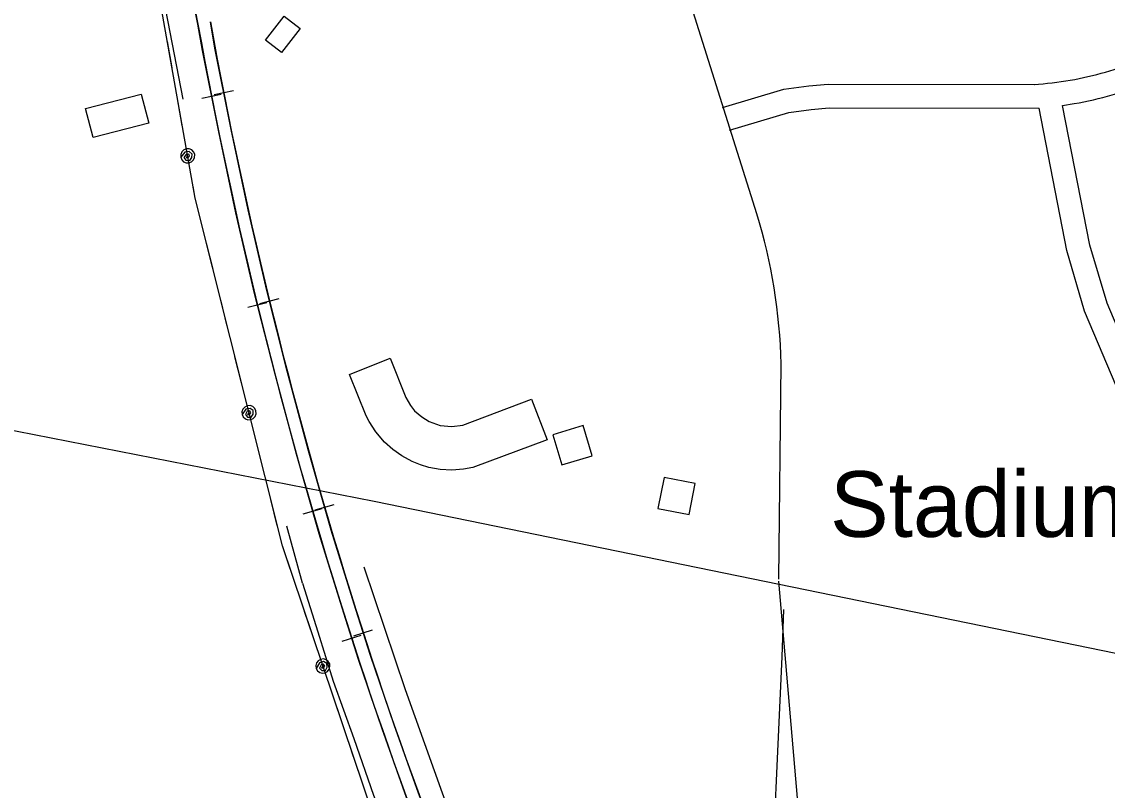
# Model space of a CAD drawing. Extents: x 3297716 to 3335574, y 688621 to 713991.
# Drawn here: x 3326177 to 3327549, y 694806 to 695778 of the extents above; entities that cross this region are included whole.
import ezdxf

# ---------------------------------------------------------------- set-up
doc = ezdxf.new("R2010")
doc.units = 0
for name, color, linetype in [('V-BLDG-IDEN', 7, 'Continuous'), ('V-BLDG-OTLN', 7, 'Continuous'), ('V-RAIL-TRAK', 7, 'Continuous'), ('V-ROAD-CNTR', 7, 'Continuous'), ('V-TOPO-SHOR', 7, 'Continuous'), ('V-UTIL-LINE', 7, 'Continuous')]:
    doc.layers.add(name, color=color, linetype=linetype)

msp = doc.modelspace()

# ---------------------------------------------------------------- linework, layer by layer
at = {"layer": 'V-BLDG-OTLN'}
for points in [[(3326485, 695754.1), (3326508.5, 695784.7), (3326528.9, 695769.1), (3326505.4, 695738.5)], [(3326257.5, 695667.8), (3326327.9, 695686), (3326337.3, 695649.4), (3326267, 695631.2)], [(3326821.3, 695300.3), (3326840.9, 695248.9), (3326747.2, 695213.7), (3326735.2, 695211.5), (3326720.6, 695210.5), (3326705.7, 695211.4), (3326691.3, 695214), (3326680.9, 695217.1), (3326670.4, 695221.4), (3326657.3, 695228.4), (3326645.9, 695236.5), (3326635.3, 695246), (3326624.4, 695258.8), (3326616, 695271.8), (3326612.2, 695279.3), (3326591.3, 695331.6), (3326642.4, 695352), (3326662.2, 695302.4), (3326668.1, 695292.2), (3326673.5, 695285.6), (3326682.5, 695277.7), (3326692.1, 695271.9), (3326705.8, 695267.1), (3326720.6, 695265.5), (3326734.6, 695267.2)], [(3326848.1, 695255.3), (3326859.7, 695217), (3326898, 695228.6), (3326886.4, 695266.9)], [(3327028.2, 695193.4), (3326988.9, 695201.2), (3326981.1, 695162), (3327020.4, 695154.2)]]:
    msp.add_lwpolyline(points, close=True, dxfattribs=at)
at = {"layer": 'V-RAIL-TRAK'}
for points in [[(3326399.5, 695774.5), (3326387.7, 695833.4), (3326377.4, 695892.2), (3326368, 695951.2), (3326359.3, 696010.8), (3326351.9, 696070.2), (3326345.7, 696129.5), (3326340, 696189.3), (3326335.8, 696249.1), (3326334.6, 696270.1)], [(3326583.9, 695029.6), (3326552.7, 695130), (3326524, 695230.6), (3326497.1, 695331.7), (3326471.1, 695433.8), (3326447.5, 695536), (3326425.9, 695638.2), (3326405.2, 695741.3), (3326399.5, 695774.5)], [(3326599.1, 695034.4), (3326568, 695134.5), (3326539.4, 695234.9), (3326512.5, 695335.7), (3326486.6, 695437.5), (3326463.2, 695539.5), (3326441.6, 695641.4), (3326421, 695744.2), (3326415.3, 695777.3)], [(3326404.6, 695680.7), (3326429.1, 695685.7)], [(3326420, 695685.6), (3326444.5, 695690.5)], [(3326477.9, 695421.2), (3326502.1, 695427.4)], [(3326462.6, 695416.4), (3326486.8, 695422.6)], [(3326547.8, 695160.1), (3326571.8, 695166.9)], [(3326532.5, 695155.3), (3326556.5, 695162.1)], [(3326841.6, 694370.6), (3326802.6, 694454.6), (3326765.8, 694539), (3326730.5, 694624.1), (3326695.8, 694710.2), (3326663.4, 694796.7), (3326632.5, 694883.3), (3326602.4, 694970.9), (3326583.9, 695029.6)], [(3326856, 694377.4), (3326817.2, 694461.2), (3326780.5, 694545.3), (3326745.3, 694630.2), (3326710.8, 694716), (3326678.4, 694802.2), (3326647.6, 694888.6), (3326617.6, 694975.9), (3326599.1, 695034.4)], [(3326581.9, 694994.2), (3326605.8, 695001.8)], [(3326596.6, 695001.1), (3326620.4, 695008.6)]]:
    msp.add_lwpolyline(points, dxfattribs=at)
for centre, radius, start, end in [((3329760.8, 696466.7), 3431.9, 183.2847, 191.637), ((3332312.7, 696842.6), 6008.8, 190.23939, 197.56166), ((3332312.7, 696842.6), 5992.8, 190.23939, 197.56166), ((3331629.5, 696622.9), 5291.2, 197.525, 205.1925), ((3331629.5, 696622.9), 5275.2, 197.525, 205.1925)]:
    msp.add_arc(centre, radius, start, end, dxfattribs=at)
at = {"layer": 'V-ROAD-CNTR'}
for points in [[(3327106.2, 695534.7), (3326979.5, 695937.7)], [(3327456.6, 695698.1), (3327462.4, 695698.5), (3327468.1, 695699), (3327473.8, 695699.6), (3327479.6, 695700.2), (3327485.3, 695700.9), (3327490.9, 695701.7), (3327496.6, 695702.6), (3327502.3, 695703.5), (3327508, 695704.5), (3327513.6, 695705.6), (3327519.2, 695706.8), (3327524.8, 695708.1), (3327530.4, 695709.4), (3327536, 695710.8), (3327541.6, 695712.3), (3327547.1, 695713.8), (3327552.6, 695715.4), (3327558.1, 695717.1), (3327563.6, 695718.9), (3327569, 695720.8), (3327574.4, 695722.7), (3327579.8, 695724.7), (3327583.5, 695726.1)], [(3327062.9, 695669.2), (3327140.1, 695692.1), (3327171.8, 695696.6), (3327196.3, 695698.5), (3327457.7, 695698.1)], [(3327492.8, 695671.5), (3327507.4, 695674), (3327513.5, 695675.1), (3327519.5, 695676.2), (3327525.5, 695677.5), (3327531.6, 695678.8), (3327537.5, 695680.2), (3327543.5, 695681.7), (3327549.4, 695683.3), (3327555.4, 695685), (3327561.3, 695686.7), (3327567.2, 695688.5), (3327573, 695690.4), (3327578.8, 695692.4), (3327584.6, 695694.5), (3327590.4, 695696.6), (3327594.2, 695698.1)], [(3327071.5, 695640.5), (3327146.5, 695662.7), (3327175, 695666.7), (3327197.4, 695668.5), (3327462.9, 695668.1)], [(3327721.7, 694936.5), (3327520.6, 695411.3), (3327498.1, 695488), (3327462.9, 695668.1)], [(3327749.3, 694948.2), (3327548.9, 695421.4), (3327527.3, 695495.1), (3327492.8, 695671.5)], [(3327134.1, 695072.5), (3327136.9, 695344.8)], [(3326063, 695280.8), (3326622.5, 695171.3), (3327611.4, 694968.5), (3328189.9, 694846.8)], [(3327164.3, 694717.1), (3327134.1, 695070)], [(3327135.5, 694375.8), (3327122.4, 694633.9), (3327138.2, 694974.6), (3327140.1, 695034.2)]]:
    msp.add_lwpolyline(points, dxfattribs=at)
msp.add_arc((3326416.5, 695325.8), 720.7, 1.5113, 16.8508, dxfattribs=at)
at = {"layer": 'V-TOPO-SHOR'}
msp.add_line((3326531.9, 695067.5), (3326511.9, 695139.7), dxfattribs=at)
for points in [[(3326380.7, 695679.6), (3326347.9, 695849.4), (3326326.3, 696007.7), (3326305.7, 696182.4), (3326290.6, 696331.6), (3326281.8, 696460.2), (3326278.2, 696519.5), (3326276.2, 696545.2), (3326277.5, 696556.5), (3326281, 696557.2), (3326293, 696557.1), (3326299.3, 696557.1)], [(3326609.1, 695088.3), (3326661.6, 694932.9), (3326745.2, 694699.8), (3326857, 694446.2), (3326967.4, 694206.4)], [(3326531.9, 695067.5), (3326551.1, 695005.8), (3326570.7, 694943.5), (3326596.5, 694871.3), (3326621.5, 694799.4), (3326644.2, 694740.5), (3326659, 694698.3), (3326690.9, 694624.4), (3326725.5, 694537.5), (3326770.8, 694431.9), (3326804.1, 694350.5), (3326851.1, 694252.8), (3326880.9, 694192.2), (3326919.6, 694114.6), (3326942.6, 694069.6), (3326970.3, 694025.7), (3326970.8, 694025)]]:
    msp.add_lwpolyline(points, dxfattribs=at)
at = {"layer": 'V-UTIL-LINE'}
for points in [[(3326949.7, 694025), (3326797, 694337.7), (3326660.2, 694658.1), (3326506.4, 695114.6), (3326396.2, 695554.3), (3326308.7, 696045.9), (3326267.3, 696515.1), (3326247.1, 696982.5), (3326229.2, 697428), (3326314.7, 697537.1)], [(3326366.9, 695719.1), (3326360.9, 695752.6)], [(3326379.8, 695646.3), (3326373.9, 695679.8)], [(3326386.6, 695607.9), (3326384.6, 695605.9), (3326386.9, 695605.4), (3326388.8, 695607.4), (3326388, 695610.2), (3326384.6, 695609.8), (3326381.8, 695606), (3326384.2, 695602.5), (3326389.1, 695602.1), (3326391.9, 695605.7), (3326392.1, 695610.1), (3326388.4, 695613.3), (3326382.9, 695612.6), (3326377.8, 695606.3), (3326379.1, 695603), (3326381.5, 695600.5), (3326384.7, 695599.1), (3326388.2, 695599), (3326391.5, 695600.3), (3326394, 695602.7), (3326395.4, 695605.9), (3326395.5, 695609.5), (3326394.2, 695612.7), (3326391.8, 695615.3), (3326388.6, 695616.7), (3326385.1, 695616.7), (3326381.8, 695615.5), (3326379.3, 695613), (3326377.8, 695609.8), (3326377.8, 695606.3)], [(3326400.7, 695536.3), (3326396.2, 695554.3), (3326393.5, 695569.5)], [(3326418.7, 695464.5), (3326410.4, 695497.5)], [(3326436.7, 695392.7), (3326428.4, 695425.7)], [(3326454.7, 695320.9), (3326446.4, 695353.9)], [(3326464.1, 695283.1), (3326462.2, 695280.9), (3326464.6, 695280.7), (3326466.3, 695282.8), (3326465.3, 695285.5), (3326462, 695284.9), (3326459.5, 695280.9), (3326462.1, 695277.6), (3326467, 695277.5), (3326469.5, 695281.3), (3326469.4, 695285.7), (3326465.5, 695288.6), (3326460.1, 695287.6), (3326455.4, 695280.9), (3326456.9, 695277.7), (3326459.5, 695275.4), (3326462.8, 695274.2), (3326466.3, 695274.4), (3326469.5, 695275.9), (3326471.9, 695278.5), (3326473, 695281.8), (3326472.9, 695285.3), (3326471.4, 695288.5), (3326468.8, 695290.8), (3326465.5, 695292), (3326462, 695291.8), (3326458.8, 695290.3), (3326456.4, 695287.7), (3326455.2, 695284.4), (3326455.4, 695280.9)], [(3326481.9, 695212.3), (3326473.6, 695245.3)], [(3326499.9, 695140.5), (3326491.6, 695173.5)], [(3326521.5, 695069.8), (3326510.6, 695102)], [(3326545.1, 694999.7), (3326534.2, 695031.9)], [(3326557.6, 694962.7), (3326555.8, 694960.4), (3326558.2, 694960.3), (3326559.8, 694962.6), (3326558.5, 694965.2), (3326555.2, 694964.3), (3326553.1, 694960.2), (3326556, 694957), (3326560.8, 694957.3), (3326563.1, 694961.3), (3326562.6, 694965.8), (3326558.5, 694968.3), (3326553.2, 694966.9), (3326549, 694959.8), (3326550.8, 694956.8), (3326553.6, 694954.7), (3326557, 694953.7), (3326560.4, 694954.2), (3326563.5, 694955.9), (3326565.6, 694958.7), (3326566.5, 694962.1), (3326566.1, 694965.6), (3326564.3, 694968.6), (3326561.6, 694970.8), (3326558.2, 694971.7), (3326554.7, 694971.2), (3326551.6, 694969.5), (3326549.5, 694966.7), (3326548.6, 694963.3), (3326549, 694959.8)], [(3326580.9, 694893.5), (3326570, 694925.8)], [(3326604.5, 694823.4), (3326593.6, 694855.6)]]:
    msp.add_lwpolyline(points, dxfattribs=at)

# ---------------------------------------------------------------- texts
at = {"layer": 'V-BLDG-IDEN'}
msp.add_text('Stadium', height=83, dxfattribs=at).set_placement((3327198.7, 695126.1))

doc.saveas('drawing.dxf')
